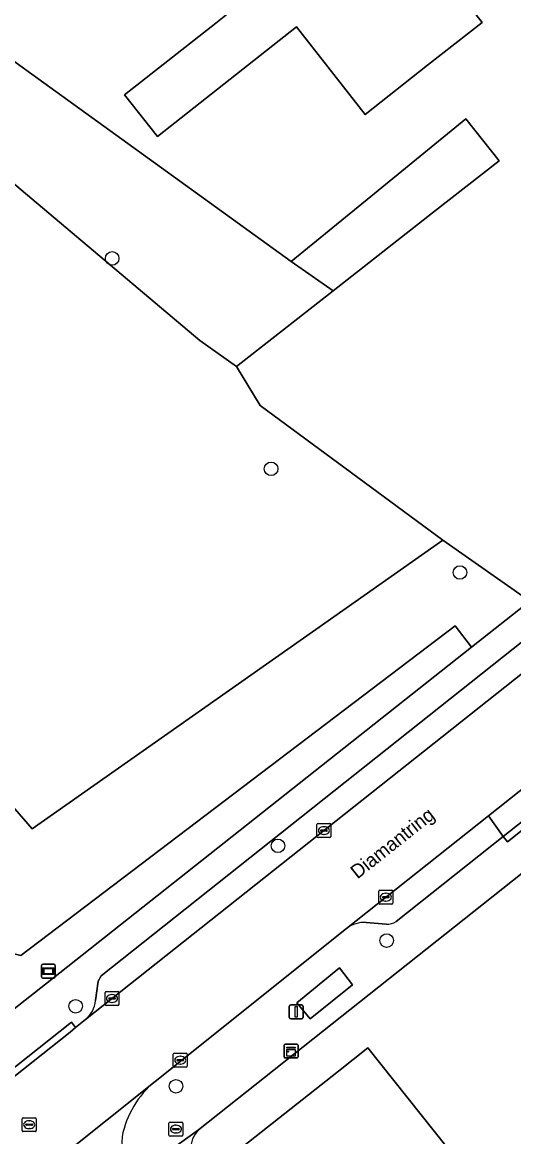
# Model space of a CAD drawing. Extents: x 159626 to 160723, y 388173 to 389416.
# Drawn here: x 160081.3 to 160116.7, y 388663.5 to 388743.7 of the extents above; entities that cross this region are included whole.
import ezdxf

# ---------------------------------------------------------------- set-up
doc = ezdxf.new("R2010")
doc.units = 0
for name, color, linetype in [('IMGEO_Boom', 7, 'Continuous'), ('IMGEO_Brandkraan', 7, 'Continuous'), ('IMGEO_Erf', 7, 'Continuous'), ('IMGEO_Groenvoorziening', 7, 'Continuous'), ('IMGEO_Houtwal', 7, 'Continuous'), ('IMGEO_Kast', 7, 'Continuous'), ('IMGEO_Kolk', 7, 'Continuous'), ('IMGEO_Lichtmast', 7, 'Continuous'), ('IMGEO_Loofbos', 7, 'Continuous'), ('IMGEO_Openbare_ruimte_label', 7, 'Continuous'), ('IMGEO_Pand', 7, 'Continuous'), ('IMGEO_Parkeervlak_open', 7, 'Continuous'), ('IMGEO_Rijbaan_lokaal_gesloten', 7, 'Continuous'), ('IMGEO_Rijbaan_lokaal_open', 7, 'Continuous'), ('IMGEO_Rioolput', 7, 'Continuous'), ('IMGEO_Verklikker', 7, 'Continuous'), ('IMGEO_Voetpad_gesloten', 7, 'Continuous'), ('IMGEO_Voetpad_open', 7, 'Continuous')]:
    doc.layers.add(name, color=color, linetype=linetype)

msp = doc.modelspace()

# ---------------------------------------------------------------- linework, layer by layer
at = {"layer": 'IMGEO_Boom'}
for centre in [(160087.809, 388726.723), (160099.254, 388711.585), (160112.86, 388704.125), (160099.748, 388684.454), (160107.579, 388677.64), (160085.175, 388672.911), (160092.405, 388667.153)]:
    msp.add_circle(centre, 0.489, dxfattribs=at)
at = {"layer": 'IMGEO_Brandkraan'}
for p, q in [((160091.9, 388663.648), (160091.9, 388664.5)), ((160091.975, 388664.574), (160092.827, 388664.574)), ((160092.388, 388664.354), (160092.413, 388664.354)), ((160092.901, 388664.5), (160092.901, 388663.648)), ((160092.827, 388663.574), (160091.975, 388663.574)), ((160092.159, 388664.068), (160092.159, 388664.08)), ((160092.597, 388664.031), (160092.199, 388664.031)), ((160092.202, 388664.117), (160092.6, 388664.117)), ((160092.411, 388663.794), (160092.386, 388663.794)), ((160092.643, 388664.08), (160092.643, 388664.068))]:
    msp.add_line(p, q, dxfattribs=at)
for points in [[(160091.9, 388663.648), (160091.9, 388664.5)], [(160091.975, 388664.574), (160092.827, 388664.574)], [(160092.901, 388664.5), (160092.901, 388663.648)], [(160092.827, 388663.574), (160091.975, 388663.574)]]:
    msp.add_lwpolyline(points, dxfattribs=at)
for centre, radius, start, end in [((160091.977, 388664.498), 0.0765, 91.55205, 178.44795), ((160091.977, 388664.498), 0.0765, 91.55205, 178.44795), ((160092.825, 388664.498), 0.0765, 1.55205, 88.44795), ((160092.825, 388664.498), 0.0765, 1.55205, 88.44795), ((160091.977, 388663.65), 0.0765, 181.55205, 268.44795), ((160091.977, 388663.65), 0.0765, 181.55205, 268.44795), ((160092.199, 388664.077), 0.0403, 85.87752, 175.75265), ((160092.196, 388664.067), 0.0366, 178.93798, 274.71019), ((160092.6, 388664.074), 0.043, 264.86636, 352.45326), ((160092.604, 388664.079), 0.0386, 1.73085, 96.63898), ((160092.825, 388663.65), 0.0765, 271.55205, 358.44795), ((160092.825, 388663.65), 0.0765, 271.55205, 358.44795)]:
    msp.add_arc(centre, radius, start, end, dxfattribs=at)
for centre, major_axis, ratio, start_param, end_param in [((160092.387, 388664.074), (-0.387, 0.002), 0.722429, 4.712389, 7.853982), ((160092.412, 388664.074), (-0.39, 0.002), 0.717154, 1.570796, 4.712389)]:
    msp.add_ellipse(centre, major_axis=major_axis, ratio=ratio, start_param=start_param, end_param=end_param, dxfattribs=at)
at = {"layer": 'IMGEO_Erf'}
for points in [[(160014.595, 388792.981), (160040.756, 388771.171), (160054.83, 388758.93), (160059.19, 388755.976), (160057.971, 388757.499), (160060.57, 388759.58), (160063.15, 388756.358), (160061.077, 388754.698), (160070.24, 388748.49), (160100.703, 388726.492), (160106.44, 388731.18), (160113.279, 388736.768), (160115.679, 388733.752), (160110.89, 388730), (160103.729, 388724.39), (160096.772, 388718.94), (160098.468, 388716.143), (160111.625, 388706.461), (160117.888, 388702.055), (160125.808, 388708.311), (160141.571, 388720.763), (160141.623, 388720.804), (160141.674, 388720.846)], [(160173.521, 388727.014), (160150.851, 388709.051), (160094.032, 388664.03)], [(160096.372, 388662.147), (160104.12, 388668.25), (160106.235, 388669.928), (160111.931, 388662.75)]]:
    msp.add_lwpolyline(points, dxfattribs=at)
msp.add_lwpolyline([(160100.531, 388747.807), (160102.559, 388745.175), (160108.719, 388750), (160109.221, 388750.393), (160109.529, 388750), (160114.459, 388743.711), (160110.53, 388740.62), (160106.041, 388737.088), (160101.088, 388743.384), (160091.065, 388735.5), (160088.703, 388738.502), (160095.265, 388743.664), (160096.602, 388744.716)], close=True, dxfattribs=at)
msp.add_arc((160095.613, 388662.538), 2.174, 136.65351, 219.72943, dxfattribs=at)
at = {"layer": 'IMGEO_Groenvoorziening'}
msp.add_lwpolyline([(160059.19, 388755.976), (160054.83, 388758.93), (160051.814, 388756.452), (160094.132, 388720.82), (160096.772, 388718.94), (160103.729, 388724.39), (160100.703, 388726.492), (160070.24, 388748.49), (160061.077, 388754.698), (160060.551, 388754.276)], close=True, dxfattribs=at)
msp.add_lwpolyline([(160080.75, 388672.717), (160083.013, 388674.507), (160113.699, 388698.746), (160112.511, 388700.291), (160081.232, 388676.573), (160078.58, 388677.212), (160044.118, 388720.119), (160042.173, 388721.999), (160039.808, 388723.459), (160038.232, 388724.113), (160036.739, 388724.533), (160035.26, 388724.75), (160037.703, 388719.251)], dxfattribs=at)
at = {"layer": 'IMGEO_Houtwal'}
msp.add_lwpolyline([(160044.194, 388729.267), (160035.207, 388725.196), (160035.26, 388724.75), (160036.739, 388724.533), (160038.232, 388724.113), (160039.808, 388723.459), (160042.173, 388721.999), (160044.118, 388720.119), (160078.58, 388677.212), (160081.232, 388676.573), (160112.511, 388700.291), (160113.699, 388698.746), (160117.888, 388702.055), (160111.625, 388706.461), (160103.114, 388700.48), (160082.042, 388685.672)], close=True, dxfattribs=at)
at = {"layer": 'IMGEO_Kast'}
for p, q in [((160100.195, 388669.264), (160100.195, 388670.105)), ((160100.195, 388670.105), (160100.195, 388669.264)), ((160100.27, 388670.189), (160101.111, 388670.189)), ((160101.111, 388670.189), (160100.27, 388670.189)), ((160101.195, 388670.114), (160101.195, 388669.273)), ((160101.195, 388669.273), (160101.195, 388670.114)), ((160101.12, 388669.189), (160100.279, 388669.189)), ((160100.279, 388669.189), (160101.12, 388669.189))]:
    msp.add_line(p, q, dxfattribs=at)
for points in [[(160100.39, 388669.979), (160100.99, 388669.979), (160100.99, 388669.894), (160100.39, 388669.894), (160100.39, 388669.979)], [(160100.39, 388669.804), (160100.99, 388669.804), (160100.99, 388669.315), (160100.39, 388669.315), (160100.39, 388669.804)]]:
    msp.add_lwpolyline(points, dxfattribs=at)
msp.add_circle((160100.474, 388669.653), 0.0377, dxfattribs=at)
for centre, start, end in [((160100.273, 388670.111), 92.4484, 184.28452), ((160100.273, 388670.111), 92.4484, 184.28452), ((160101.117, 388670.111), 2.4484, 94.28452), ((160101.117, 388670.111), 2.4484, 94.28452), ((160100.273, 388669.267), 182.4484, 274.28452), ((160100.273, 388669.267), 182.4484, 274.28452), ((160101.117, 388669.267), 272.4484, 4.28452), ((160101.117, 388669.267), 272.4484, 4.28452)]:
    msp.add_arc(centre, 0.0779, start, end, dxfattribs=at)
at = {"layer": 'IMGEO_Kolk'}
for p, q in [((160102.559, 388685.129), (160102.559, 388685.981)), ((160102.634, 388686.055), (160103.486, 388686.055)), ((160103.047, 388685.835), (160103.072, 388685.835)), ((160103.56, 388685.981), (160103.56, 388685.129)), ((160103.486, 388685.055), (160102.634, 388685.055)), ((160102.818, 388685.549), (160102.818, 388685.561)), ((160103.256, 388685.512), (160102.858, 388685.512)), ((160102.861, 388685.598), (160103.259, 388685.598)), ((160103.07, 388685.275), (160103.045, 388685.275)), ((160103.302, 388685.561), (160103.302, 388685.549)), ((160107.019, 388680.337), (160107.019, 388681.189)), ((160107.094, 388681.263), (160107.946, 388681.263)), ((160107.507, 388681.043), (160107.532, 388681.043)), ((160108.02, 388681.189), (160108.02, 388680.337)), ((160107.946, 388680.263), (160107.094, 388680.263)), ((160107.278, 388680.757), (160107.278, 388680.769)), ((160107.716, 388680.72), (160107.318, 388680.72)), ((160107.321, 388680.806), (160107.719, 388680.806)), ((160107.53, 388680.483), (160107.505, 388680.483)), ((160107.762, 388680.769), (160107.762, 388680.757)), ((160087.297, 388673.042), (160087.297, 388673.894)), ((160087.372, 388673.968), (160088.224, 388673.968)), ((160088.298, 388673.894), (160088.298, 388673.042)), ((160088.224, 388672.968), (160087.372, 388672.968)), ((160087.556, 388673.462), (160087.556, 388673.474)), ((160087.994, 388673.425), (160087.596, 388673.425)), ((160087.599, 388673.511), (160087.997, 388673.511)), ((160087.808, 388673.188), (160087.783, 388673.188)), ((160087.785, 388673.748), (160087.81, 388673.748)), ((160088.04, 388673.474), (160088.04, 388673.462)), ((160092.211, 388668.606), (160092.211, 388669.458)), ((160092.286, 388669.532), (160093.138, 388669.532)), ((160092.47, 388669.026), (160092.47, 388669.038)), ((160092.908, 388668.989), (160092.51, 388668.989)), ((160092.513, 388669.075), (160092.911, 388669.075)), ((160092.699, 388669.312), (160092.724, 388669.312)), ((160092.954, 388669.038), (160092.954, 388669.026)), ((160093.212, 388669.458), (160093.212, 388668.606)), ((160093.138, 388668.532), (160092.286, 388668.532)), ((160092.722, 388668.752), (160092.697, 388668.752))]:
    msp.add_line(p, q, dxfattribs=at)
for points in [[(160102.559, 388685.129), (160102.559, 388685.981)], [(160102.634, 388686.055), (160103.486, 388686.055)], [(160103.56, 388685.981), (160103.56, 388685.129)], [(160103.486, 388685.055), (160102.634, 388685.055)], [(160107.019, 388680.337), (160107.019, 388681.189)], [(160107.094, 388681.263), (160107.946, 388681.263)], [(160108.02, 388681.189), (160108.02, 388680.337)], [(160107.946, 388680.263), (160107.094, 388680.263)], [(160087.297, 388673.042), (160087.297, 388673.894)], [(160087.372, 388673.968), (160088.224, 388673.968)], [(160088.298, 388673.894), (160088.298, 388673.042)], [(160088.224, 388672.968), (160087.372, 388672.968)], [(160092.211, 388668.606), (160092.211, 388669.458)], [(160092.286, 388669.532), (160093.138, 388669.532)], [(160093.212, 388669.458), (160093.212, 388668.606)], [(160093.138, 388668.532), (160092.286, 388668.532)]]:
    msp.add_lwpolyline(points, dxfattribs=at)
for centre, radius, start, end in [((160102.636, 388685.979), 0.0765, 91.55205, 178.44795), ((160102.636, 388685.979), 0.0765, 91.55205, 178.44795), ((160103.484, 388685.979), 0.0765, 1.55205, 88.44795), ((160103.484, 388685.979), 0.0765, 1.55205, 88.44795), ((160102.636, 388685.131), 0.0765, 181.55205, 268.44795), ((160102.636, 388685.131), 0.0765, 181.55205, 268.44795), ((160102.858, 388685.558), 0.0403, 85.87752, 175.75265), ((160102.855, 388685.548), 0.0366, 178.93798, 274.71019), ((160103.259, 388685.555), 0.043, 264.86636, 352.45326), ((160103.263, 388685.56), 0.0386, 1.73085, 96.63898), ((160103.484, 388685.131), 0.0765, 271.55205, 358.44795), ((160103.484, 388685.131), 0.0765, 271.55205, 358.44795), ((160107.096, 388681.187), 0.0765, 91.55205, 178.44795), ((160107.096, 388681.187), 0.0765, 91.55205, 178.44795), ((160107.944, 388681.187), 0.0765, 1.55205, 88.44795), ((160107.944, 388681.187), 0.0765, 1.55205, 88.44795), ((160107.096, 388680.339), 0.0765, 181.55205, 268.44795), ((160107.096, 388680.339), 0.0765, 181.55205, 268.44795), ((160107.318, 388680.766), 0.0403, 85.87752, 175.75265), ((160107.315, 388680.756), 0.0366, 178.93798, 274.71019), ((160107.719, 388680.763), 0.043, 264.86636, 352.45326), ((160107.723, 388680.768), 0.0386, 1.73085, 96.63898), ((160107.944, 388680.339), 0.0765, 271.55205, 358.44795), ((160107.944, 388680.339), 0.0765, 271.55205, 358.44795), ((160087.374, 388673.892), 0.0765, 91.55205, 178.44795), ((160087.374, 388673.892), 0.0765, 91.55205, 178.44795), ((160088.222, 388673.892), 0.0765, 1.55205, 88.44795), ((160088.222, 388673.892), 0.0765, 1.55205, 88.44795), ((160087.374, 388673.044), 0.0765, 181.55205, 268.44795), ((160087.374, 388673.044), 0.0765, 181.55205, 268.44795), ((160087.596, 388673.471), 0.0403, 85.87752, 175.75265), ((160087.593, 388673.461), 0.0366, 178.93798, 274.71019), ((160087.997, 388673.468), 0.043, 264.86636, 352.45326), ((160088.001, 388673.473), 0.0386, 1.73085, 96.63898), ((160088.222, 388673.044), 0.0765, 271.55205, 358.44795), ((160088.222, 388673.044), 0.0765, 271.55205, 358.44795), ((160092.288, 388669.456), 0.0765, 91.55205, 178.44795), ((160092.288, 388669.456), 0.0765, 91.55205, 178.44795), ((160092.51, 388669.035), 0.0403, 85.87752, 175.75265), ((160092.507, 388669.025), 0.0366, 178.93798, 274.71019), ((160092.911, 388669.032), 0.043, 264.86636, 352.45326), ((160092.915, 388669.037), 0.0386, 1.73085, 96.63898), ((160093.136, 388669.456), 0.0765, 1.55205, 88.44795), ((160093.136, 388669.456), 0.0765, 1.55205, 88.44795), ((160092.288, 388668.608), 0.0765, 181.55205, 268.44795), ((160092.288, 388668.608), 0.0765, 181.55205, 268.44795), ((160093.136, 388668.608), 0.0765, 271.55205, 358.44795), ((160093.136, 388668.608), 0.0765, 271.55205, 358.44795)]:
    msp.add_arc(centre, radius, start, end, dxfattribs=at)
for centre, major_axis, ratio, start_param, end_param in [((160103.046, 388685.555), (-0.387, 0.002), 0.722429, 4.712389, 7.853982), ((160103.071, 388685.555), (-0.39, 0.002), 0.717154, 1.570796, 4.712389), ((160107.506, 388680.763), (-0.387, 0.002), 0.722429, 4.712389, 7.853982), ((160107.531, 388680.763), (-0.39, 0.002), 0.717154, 1.570796, 4.712389), ((160087.784, 388673.468), (-0.387, 0.002), 0.722429, 4.712389, 7.853982), ((160087.809, 388673.468), (-0.39, 0.002), 0.717154, 1.570796, 4.712389), ((160092.698, 388669.032), (-0.387, 0.002), 0.722429, 4.712389, 7.853982), ((160092.723, 388669.032), (-0.39, 0.002), 0.717154, 1.570796, 4.712389)]:
    msp.add_ellipse(centre, major_axis=major_axis, ratio=ratio, start_param=start_param, end_param=end_param, dxfattribs=at)
at = {"layer": 'IMGEO_Lichtmast'}
for p, q in [((160100.668, 388673.009), (160101.458, 388673.009)), ((160101.458, 388673.009), (160100.668, 388673.009)), ((160100.568, 388672.109), (160100.568, 388672.909)), ((160100.568, 388672.909), (160100.568, 388672.109)), ((160101.558, 388672.909), (160101.558, 388672.109)), ((160101.558, 388672.109), (160101.558, 388672.909)), ((160101.458, 388672.009), (160100.668, 388672.009)), ((160100.668, 388672.009), (160101.458, 388672.009))]:
    msp.add_line(p, q, dxfattribs=at)
msp.add_lwpolyline([(160100.988, 388672.884), (160101.138, 388672.884), (160101.138, 388672.134), (160100.988, 388672.134), (160100.988, 388672.884)], dxfattribs=at)
for centre, start, end in [((160100.668, 388672.909), 90, 180), ((160100.668, 388672.909), 90, 180), ((160101.458, 388672.909), 0, 90), ((160101.458, 388672.909), 360, 90), ((160100.668, 388672.109), 180, 270), ((160100.668, 388672.109), 180, 270), ((160101.458, 388672.109), 270, 0), ((160101.458, 388672.109), 270, 0)]:
    msp.add_arc(centre, 0.1, start, end, dxfattribs=at)
at = {"layer": 'IMGEO_Loofbos'}
msp.add_lwpolyline([(160054.83, 388758.93), (160040.756, 388771.171), (160014.595, 388792.981), (159991.391, 388807.51), (159991.259, 388807.186), (159990.759, 388805.958), (159990.39, 388805.138), (159999.083, 388798.016), (160004.305, 388794.958), (160012.777, 388792.581), (160019.989, 388786.421), (160024.301, 388779.741), (160025.508, 388770.069), (160029.188, 388752.383), (160032.717, 388745.975), (160035.207, 388725.196), (160044.194, 388729.267), (160082.042, 388685.672), (160103.114, 388700.48), (160111.625, 388706.461), (160098.468, 388716.143), (160096.772, 388718.94), (160094.132, 388720.82), (160051.814, 388756.452)], close=True, dxfattribs=at)
at = {"layer": 'IMGEO_Pand'}
for points in [[(160096.602, 388744.716), (160095.265, 388743.664), (160088.703, 388738.502), (160091.065, 388735.5), (160101.088, 388743.384), (160106.041, 388737.088), (160110.53, 388740.62), (160114.459, 388743.711), (160109.529, 388750), (160109.221, 388750.393), (160108.719, 388750), (160102.559, 388745.175), (160100.531, 388747.807)], [(160100.703, 388726.492), (160103.729, 388724.39), (160110.89, 388730), (160115.679, 388733.752), (160113.279, 388736.768), (160106.44, 388731.18)], [(160110.792, 388661.85), (160111.931, 388662.75), (160106.235, 388669.928), (160104.12, 388668.25), (160096.372, 388662.147), (160100.126, 388657.411), (160103.137, 388659.818), (160104.13, 388660.611), (160106.1, 388658.145)]]:
    msp.add_lwpolyline(points, close=True, dxfattribs=at)
at = {"layer": 'IMGEO_Parkeervlak_open'}
for points in [[(160085.885, 388671.953), (160143.177, 388717.325)], [(160139.612, 388716.804), (160087.01, 388675.096), (160086.793, 388674.715), (160086.598, 388673.317)], [(160115.979, 388685.129), (160114.92, 388686.617), (160104.695, 388678.512)], [(160108.268, 388679.018), (160115.979, 388685.129)], [(160106.098, 388678.948), (160107.546, 388678.817)]]:
    msp.add_lwpolyline(points, dxfattribs=at)
msp.add_lwpolyline([(160118.949, 388687.484), (160117.817, 388688.912), (160114.92, 388686.617), (160115.979, 388685.129)], close=True, dxfattribs=at)
for centre, radius, start, end in [((160105.994, 388676.808), 2.143, 87.21627, 127.31032), ((160107.587, 388680.066), 1.25, 268.11255, 303.00115), ((160084.62, 388673.483), 1.985, 309.59689, 355.20852)]:
    msp.add_arc(centre, radius, start, end, dxfattribs=at)
at = {"layer": 'IMGEO_Rijbaan_lokaal_gesloten'}
for points in [[(160167.383, 388736.528), (160164.446, 388734.198), (160154.322, 388726.169), (160153.45, 388725.499), (160143.876, 388717.854), (160143.646, 388717.671), (160143.177, 388717.325), (160085.885, 388671.953), (160085.177, 388671.383), (160084.775, 388671.059), (160074.107, 388662.597), (160068.619, 388658.215), (160050.132, 388643.587), (160047.169, 388641.243), (160035.367, 388631.905), (160032.398, 388629.556), (160020.566, 388620.194), (160017.62, 388617.863), (160009.366, 388611.332), (160008.998, 388611.041), (160000, 388603.924), (159995.738, 388600.553), (159983.064, 388590.517)], [(160076.921, 388656.375), (160090.898, 388667.506), (160104.695, 388678.512), (160114.92, 388686.617), (160117.817, 388688.912), (160122.521, 388692.641), (160125.504, 388695.005), (160129.729, 388698.354), (160132.7, 388700.709), (160137.417, 388704.448), (160140.4, 388706.812), (160145.108, 388710.543), (160148.116, 388712.927), (160152.872, 388716.695), (160155.799, 388719.014), (160160.515, 388722.751), (160163.509, 388725.123), (160170.527, 388730.683), (160171.328, 388731.319)]]:
    msp.add_lwpolyline(points, dxfattribs=at)
at = {"layer": 'IMGEO_Rijbaan_lokaal_open'}
msp.add_lwpolyline([(160090.898, 388667.506), (160076.921, 388656.375)], dxfattribs=at)
for centre, radius, start, end in [((160095.232, 388662.218), 6.837, 129.33328, 168.95969), ((160094.642, 388663.021), 6.142, 175.27644, 204.80948)]:
    msp.add_arc(centre, radius, start, end, dxfattribs=at)
at = {"layer": 'IMGEO_Rioolput'}
for p, q in [((160081.331, 388663.964), (160081.331, 388664.816)), ((160081.406, 388664.89), (160082.258, 388664.89)), ((160081.59, 388664.384), (160081.59, 388664.396)), ((160082.028, 388664.347), (160081.63, 388664.347)), ((160081.633, 388664.433), (160082.031, 388664.433)), ((160081.819, 388664.67), (160081.844, 388664.67)), ((160082.074, 388664.396), (160082.074, 388664.384)), ((160082.332, 388664.816), (160082.332, 388663.964)), ((160082.258, 388663.89), (160081.406, 388663.89)), ((160081.842, 388664.11), (160081.817, 388664.11))]:
    msp.add_line(p, q, dxfattribs=at)
for points in [[(160081.331, 388663.964), (160081.331, 388664.816)], [(160081.406, 388664.89), (160082.258, 388664.89)], [(160082.332, 388664.816), (160082.332, 388663.964)], [(160082.258, 388663.89), (160081.406, 388663.89)]]:
    msp.add_lwpolyline(points, dxfattribs=at)
for centre, radius, start, end in [((160081.408, 388664.814), 0.0765, 91.55205, 178.44795), ((160081.408, 388664.814), 0.0765, 91.55205, 178.44795), ((160081.63, 388664.393), 0.0403, 85.87752, 175.75265), ((160081.627, 388664.383), 0.0366, 178.93798, 274.71019), ((160082.031, 388664.39), 0.043, 264.86636, 352.45326), ((160082.035, 388664.395), 0.0386, 1.73085, 96.63898), ((160082.256, 388664.814), 0.0765, 1.55205, 88.44795), ((160082.256, 388664.814), 0.0765, 1.55205, 88.44795), ((160081.408, 388663.966), 0.0765, 181.55205, 268.44795), ((160081.408, 388663.966), 0.0765, 181.55205, 268.44795), ((160082.256, 388663.966), 0.0765, 271.55205, 358.44795), ((160082.256, 388663.966), 0.0765, 271.55205, 358.44795)]:
    msp.add_arc(centre, radius, start, end, dxfattribs=at)
for centre, major_axis, ratio, start_param, end_param in [((160081.818, 388664.39), (-0.387, 0.002), 0.722429, 4.712389, 7.853982), ((160081.843, 388664.39), (-0.39, 0.002), 0.717154, 1.570796, 4.712389)]:
    msp.add_ellipse(centre, major_axis=major_axis, ratio=ratio, start_param=start_param, end_param=end_param, dxfattribs=at)
at = {"layer": 'IMGEO_Verklikker'}
for p, q in [((160082.719, 388675.037), (160082.719, 388675.837)), ((160082.719, 388675.837), (160082.719, 388675.037)), ((160082.819, 388675.937), (160083.609, 388675.937)), ((160083.609, 388675.937), (160082.819, 388675.937)), ((160083.709, 388675.837), (160083.709, 388675.037)), ((160083.709, 388675.037), (160083.709, 388675.837)), ((160083.609, 388674.937), (160082.819, 388674.937)), ((160082.819, 388674.937), (160083.609, 388674.937))]:
    msp.add_line(p, q, dxfattribs=at)
for points in [[(160082.82, 388675.669), (160083.608, 388675.669), (160083.608, 388675.205), (160082.82, 388675.205), (160082.82, 388675.669)], [(160082.885, 388675.604), (160082.885, 388675.27), (160083.543, 388675.27), (160083.543, 388675.604), (160082.885, 388675.604)]]:
    msp.add_lwpolyline(points, dxfattribs=at)
for centre, start, end in [((160082.819, 388675.837), 90, 180), ((160082.819, 388675.837), 90, 180), ((160083.609, 388675.837), 0, 90), ((160083.609, 388675.837), 360, 90), ((160082.819, 388675.037), 180, 270), ((160082.819, 388675.037), 180, 270), ((160083.609, 388675.037), 270, 0), ((160083.609, 388675.037), 270, 0)]:
    msp.add_arc(centre, 0.1, start, end, dxfattribs=at)
at = {"layer": 'IMGEO_Voetpad_gesloten'}
msp.add_lwpolyline([(160101.108, 388673.158), (160102.071, 388672.008), (160105.116, 388674.457), (160104.176, 388675.683)], close=True, dxfattribs=at)
at = {"layer": 'IMGEO_Voetpad_open'}
for points in [[(160089.067, 388660.444), (160094.032, 388664.03), (160150.851, 388709.051), (160173.521, 388727.014)], [(160143.177, 388717.325), (160143.646, 388717.671), (160142.947, 388718.554), (160143.176, 388718.737), (160141.571, 388720.763), (160125.808, 388708.311), (160117.888, 388702.055), (160113.699, 388698.746), (160083.013, 388674.507), (160080.75, 388672.717)], [(160086.598, 388673.317), (160086.793, 388674.715), (160087.01, 388675.096), (160139.612, 388716.804)], [(160119.246, 388687.104), (160116.278, 388684.736), (160115.979, 388685.129), (160108.268, 388679.018)], [(160107.546, 388678.817), (160106.098, 388678.948)], [(160104.695, 388678.512), (160090.898, 388667.506)], [(160074.107, 388662.597), (160073.797, 388662.988), (160084.867, 388671.774), (160085.177, 388671.383), (160085.885, 388671.953)], [(160094.032, 388664.03), (160089.067, 388660.444)]]:
    msp.add_lwpolyline(points, dxfattribs=at)
for points in [[(160118.949, 388687.484), (160115.979, 388685.129), (160116.278, 388684.736), (160119.246, 388687.104)], [(160101.108, 388673.158), (160104.176, 388675.683), (160105.116, 388674.457), (160102.071, 388672.008)], [(160074.107, 388662.597), (160084.775, 388671.059), (160085.177, 388671.383), (160084.867, 388671.774), (160073.797, 388662.988)]]:
    msp.add_lwpolyline(points, close=True, dxfattribs=at)
for centre, radius, start, end in [((160105.994, 388676.808), 2.143, 87.21627, 127.31032), ((160107.587, 388680.066), 1.25, 268.11255, 303.00115), ((160084.62, 388673.483), 1.985, 309.59689, 355.20852), ((160095.232, 388662.218), 6.837, 129.33328, 168.95969), ((160094.642, 388663.021), 6.142, 175.27644, 204.80948), ((160095.613, 388662.538), 2.174, 136.65351, 219.72943)]:
    msp.add_arc(centre, radius, start, end, dxfattribs=at)

# ---------------------------------------------------------------- texts
at = {"layer": 'IMGEO_Openbare_ruimte_label'}
msp.add_text('Diamantring', height=1, rotation=38.38246, dxfattribs=at).set_placement((160105.474, 388682.029))

doc.saveas('drawing.dxf')
